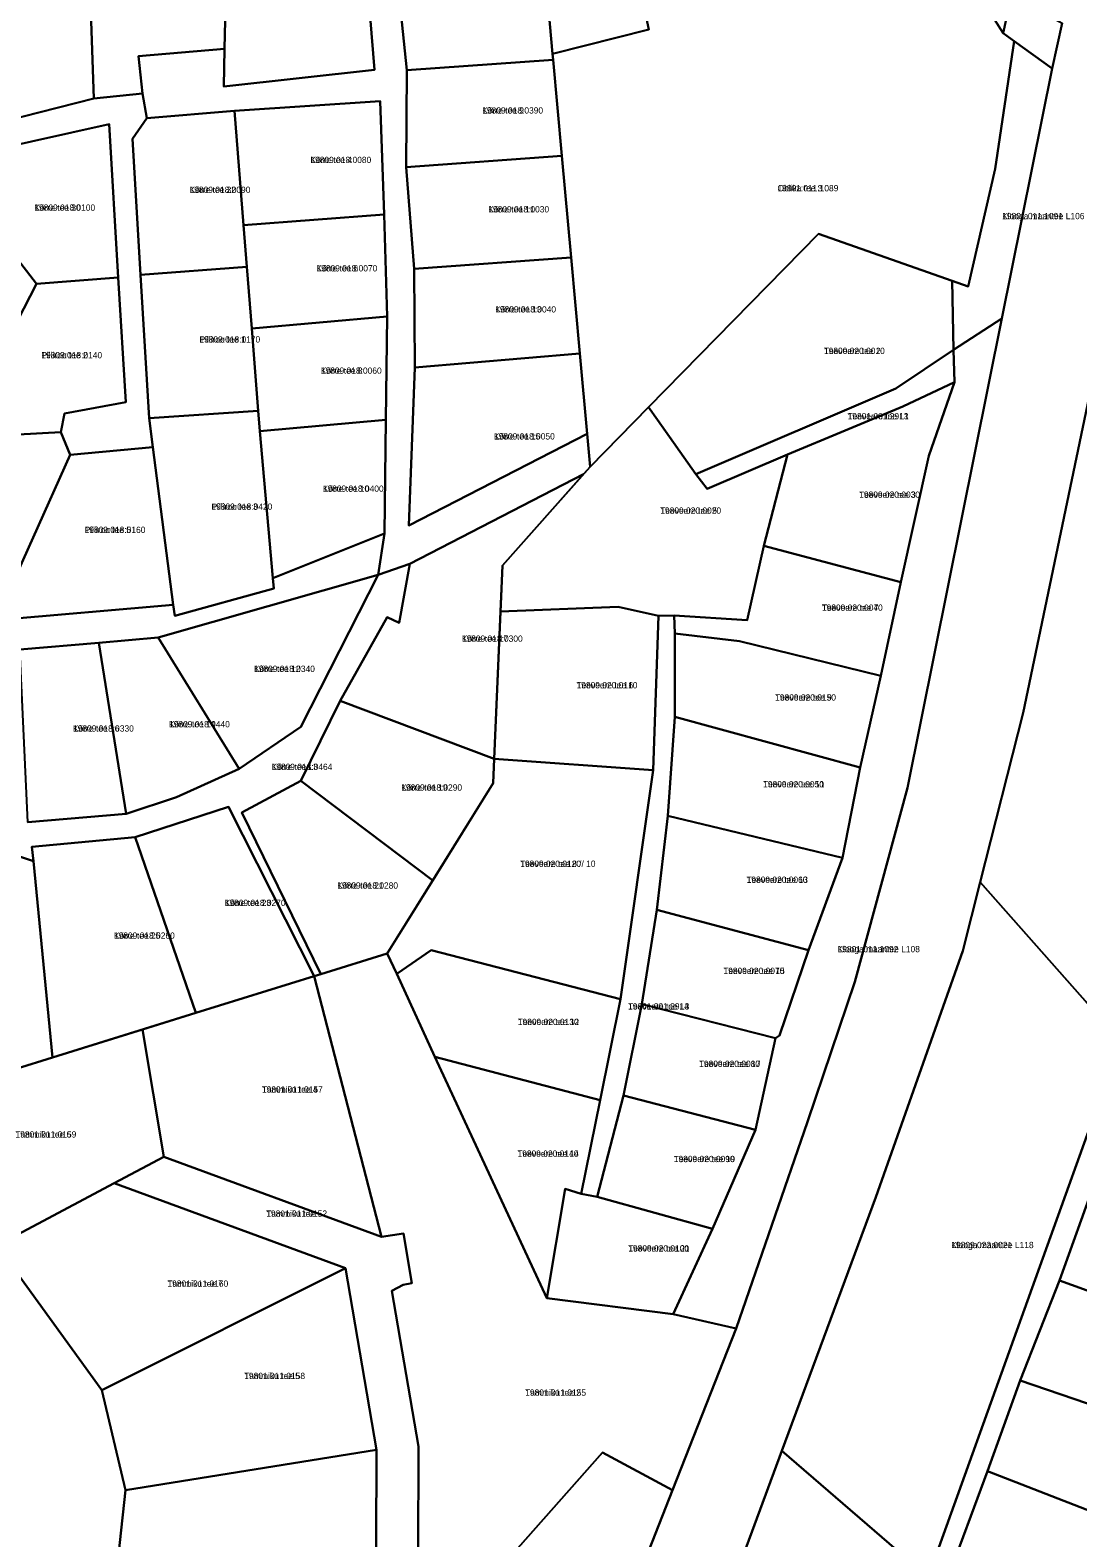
# Model space of a CAD drawing. Extents: x 516875 to 535633, y 6574491 to 6593094.
# Drawn here: x 520822.5 to 521072.3, y 6588801.2 to 6589160.7 of the extents above; entities that cross this region are included whole.
import ezdxf

# ---------------------------------------------------------------- set-up
doc = ezdxf.new("R2010")
doc.units = 0
for name, color, linetype in [('L_AADRESS', 7, 'Continuous'), ('PIIR', 7, 'Continuous'), ('TUNNUS', 7, 'Continuous')]:
    doc.layers.add(name, color=color, linetype=linetype)

msp = doc.modelspace()

# ---------------------------------------------------------------- linework, layer by layer
at = {"layer": 'PIIR'}
for points in [[(521113.51, 6589249.45), (521092.52, 6589148.09), (521087.53, 6589123.96), (521083.31, 6589112.79), (521082.46, 6589109.06), (521059.2, 6588997.94), (521048.96, 6588957.54), (521044.82, 6588941.2), (521024.12, 6588882.43), (521001.72, 6588821.95), (520983.52, 6588772.71), (520963.93, 6588719.79), (520946.47, 6588679.21), (520933.42, 6588646.06), (520903.87, 6588571.37), (520882.33, 6588519.13), (520878.26, 6588511.09), (520866.55, 6588488.59), (520853.91, 6588466.49), (520850.01, 6588439), (520821.3, 6588417.77), (520787.99, 6588379.19), (520704.64, 6588282.63)], [(520909.92, 6589174.34), (520912.31, 6589151.18), (520912.12, 6589128.02), (520914, 6589103.77), (520914.19, 6589080.27), (520912.78, 6589042.6), (520955.26, 6589064.5), (520955.98, 6589056.58), (520954.42, 6589054.82), (520913.03, 6589033.48), (520905.42, 6589030.81), (520906.95, 6589040.68), (520907.29, 6589067.78), (520907.6, 6589092.43), (520906.86, 6589116.75), (520905.91, 6589143.81), (520871.18, 6589141.44), (520850.26, 6589139.71), (520849.26, 6589145.62), (520848.29, 6589154.49), (520868.85, 6589156.27), (520868.64, 6589147.27), (520904.56, 6589151.22), (520902.12, 6589181.49)], [(521057.52, 6589173.82), (521054.48, 6589159.96), (521047.74, 6589170.69)], [(520895.13, 6588603.37), (520906.22, 6588632.62), (520914.49, 6588654.46), (520922.61, 6588675.88), (520933.69, 6588705.13), (520940.87, 6588724.07), (520975.66, 6588812.61), (520990.8, 6588851.14), (521007.83, 6588900.4), (521019.1, 6588933.81), (521031.62, 6588980.07), (521054.14, 6589091.98), (521066.15, 6589151.6), (521068.57, 6589162.41)], [(520812, 6589137.9), (520837.7, 6589144.4), (520849.26, 6589145.62), (520850.26, 6589139.71), (520846.85, 6589134.82), (520848.8, 6589102.35), (520850.85, 6589068.2), (520851.75, 6589061.26), (520831.99, 6589059.46), (520829.77, 6589064.85), (520830.67, 6589069.3), (520845.28, 6589072.02), (520843.5, 6589101.77), (520841.31, 6589138.3), (520813.82, 6589132.18)], [(520821.89, 6588971.86), (520845.4, 6588973.88), (520857.41, 6588977.79), (520872.35, 6588984.58), (520886.98, 6588994.59), (520905.42, 6589030.81), (520913.03, 6589033.48), (520910.44, 6589019.39), (520907.6, 6589020.73), (520896.4, 6589000.78), (520887.01, 6588981.75), (520872.92, 6588974.16), (520891.76, 6588935.63), (520890.23, 6588935.16), (520869.78, 6588975.54), (520847.54, 6588968.29), (520822.91, 6588966.01), (520823.25, 6588962.53), (520805.04, 6588968.64)], [(520980.19, 6588617.08), (520985.36, 6588632.85), (520998.05, 6588671.53), (521011.5, 6588712.52), (521024.12, 6588748.37), (521038.62, 6588790.13), (521036.62, 6588791.86), (521082.48, 6588919.64)], [(521076.41, 6588886.27), (521067.86, 6588862.57), (521058.55, 6588838.76), (521050.74, 6588817.12), (521040.94, 6588790.72), (521032.53, 6588767.91), (521023.22, 6588743.21), (521015.86, 6588719.54), (521007.08, 6588695.11), (521001.14, 6588675.67), (521049, 6588669.55), (521052.14, 6588689.49), (521056.24, 6588707.52), (521062.16, 6588730.29), (521071.09, 6588753.38), (521079.2, 6588776.74)]]:
    msp.add_lwpolyline(points, dxfattribs=at)
for points in [[(520868.85, 6589156.27), (520869.81, 6589196.87), (520896.77, 6589203.66), (520893.44, 6589182.16), (520902.12, 6589181.49), (520904.56, 6589151.22), (520868.64, 6589147.27)], [(520849.26, 6589145.62), (520837.7, 6589144.4), (520836.13, 6589188.38), (520869.81, 6589196.87), (520868.85, 6589156.27), (520848.29, 6589154.49)], [(520987.96, 6589174.63), (520968.11, 6589169.8), (520970.02, 6589160.88), (520947.01, 6589155.08), (520945.13, 6589176.57), (520944.66, 6589181.9), (520984.15, 6589192.47)], [(520798.28, 6589180.89), (520804.26, 6589180.35), (520836.13, 6589188.38), (520837.7, 6589144.4), (520812, 6589137.9)], [(520947.01, 6589155.08), (520970.02, 6589160.88), (520968.11, 6589169.8), (520987.96, 6589174.63), (521016.35, 6589179.45), (521032.69, 6589188.01), (521043.78, 6589179.35), (521047.74, 6589170.69), (521054.48, 6589159.96), (521057.05, 6589158.12), (521052.59, 6589127.66), (521046.1, 6589099.58), (521042.31, 6589100.91), (521010.47, 6589112.11), (520969.9, 6589070.8), (520955.98, 6589056.58), (520955.26, 6589064.5), (520953.52, 6589083.62), (520951.43, 6589106.53), (520949.23, 6589130.73), (520947.14, 6589153.64)], [(520909.92, 6589174.34), (520945.13, 6589176.57), (520947.01, 6589155.08), (520947.14, 6589153.64), (520912.31, 6589151.18)], [(521057.52, 6589173.82), (521062.76, 6589165.56), (521068.57, 6589162.41), (521066.15, 6589151.6), (521057.05, 6589158.12), (521054.48, 6589159.96)], [(521057.05, 6589158.12), (521066.15, 6589151.6), (521054.14, 6589091.98), (521042.6, 6589084.49), (521042.31, 6589100.91), (521046.1, 6589099.58), (521052.59, 6589127.66)], [(520912.31, 6589151.18), (520947.14, 6589153.64), (520949.23, 6589130.73), (520912.12, 6589128.02)], [(520871.18, 6589141.44), (520905.91, 6589143.81), (520906.86, 6589116.75), (520873.34, 6589114.23)], [(520846.85, 6589134.82), (520850.26, 6589139.71), (520871.18, 6589141.44), (520873.34, 6589114.23), (520874.13, 6589104.31), (520848.8, 6589102.35)], [(520803.45, 6589126.82), (520813.82, 6589132.18), (520841.31, 6589138.3), (520843.5, 6589101.77), (520824.03, 6589100.25)], [(520912.12, 6589128.02), (520949.23, 6589130.73), (520951.43, 6589106.53), (520914, 6589103.77)], [(520793.05, 6589117.2), (520803.45, 6589126.82), (520824.03, 6589100.25), (520816.35, 6589085.4), (520784.93, 6589100.75)], [(520874.13, 6589104.31), (520873.34, 6589114.23), (520906.86, 6589116.75), (520907.6, 6589092.43), (520875.3, 6589089.61)], [(521042.31, 6589100.91), (521042.6, 6589084.49), (521028.86, 6589075.25), (520981.21, 6589054.87), (520972.05, 6589067.78), (520969.9, 6589070.8), (521010.47, 6589112.11)], [(521083.31, 6589112.79), (521123.75, 6589097.54), (521112.7, 6589041.66), (521089.72, 6588939.81), (521082.48, 6588919.64), (521048.96, 6588957.54), (521059.2, 6588997.94), (521082.46, 6589109.06)], [(520848.8, 6589102.35), (520874.13, 6589104.31), (520875.3, 6589089.61), (520876.86, 6589069.97), (520850.85, 6589068.2)], [(520914, 6589103.77), (520951.43, 6589106.53), (520953.52, 6589083.62), (520914.19, 6589080.27)], [(520805.01, 6589063.48), (520816.35, 6589085.4), (520824.03, 6589100.25), (520843.5, 6589101.77), (520845.28, 6589072.02), (520830.67, 6589069.3), (520829.77, 6589064.85)], [(520876.86, 6589069.97), (520875.3, 6589089.61), (520907.6, 6589092.43), (520907.29, 6589067.78), (520877.23, 6589065.13)], [(521042.6, 6589084.49), (521054.14, 6589091.98), (521031.62, 6588980.07), (521019.1, 6588933.81), (521007.83, 6588900.4), (520990.8, 6588851.14), (520975.81, 6588854.53), (520985.14, 6588874.9), (520995.42, 6588898.53), (521000.2, 6588920.37), (521001.13, 6588920.98), (521008.04, 6588941.38), (521016.17, 6588963.35), (521020.41, 6588984.9), (521025.3, 6589006.75), (521030.06, 6589029.11), (521036.72, 6589059.25), (521042.89, 6589076.79)], [(520914.19, 6589080.27), (520953.52, 6589083.62), (520955.26, 6589064.5), (520912.78, 6589042.6)], [(521028.86, 6589075.25), (521042.6, 6589084.49), (521042.89, 6589076.79), (521030.52, 6589071), (521003.07, 6589059.55), (520983.87, 6589051.31), (520981.21, 6589054.87)], [(521036.72, 6589059.25), (521030.06, 6589029.11), (520997.4, 6589037.78), (521003.07, 6589059.55), (521030.52, 6589071), (521042.89, 6589076.79)], [(520972.05, 6589067.78), (520981.21, 6589054.87), (520983.87, 6589051.31), (521003.07, 6589059.55), (520997.4, 6589037.78), (520993.4, 6589020.02), (520976.05, 6589021.13), (520972.29, 6589021.1), (520962.65, 6589023.24), (520934.59, 6589022.08), (520935.06, 6589033.05), (520955.98, 6589056.58), (520969.9, 6589070.8)], [(520856.6, 6589023.71), (520851.75, 6589061.26), (520850.85, 6589068.2), (520876.86, 6589069.97), (520877.23, 6589065.13), (520880.36, 6589030.08), (520880.58, 6589027.59), (520856.94, 6589021.08)], [(520877.23, 6589065.13), (520907.29, 6589067.78), (520906.95, 6589040.68), (520880.36, 6589030.08)], [(520793.96, 6589042.11), (520805.01, 6589063.48), (520829.77, 6589064.85), (520831.99, 6589059.46), (520814.31, 6589020.02), (520783.08, 6589021.07)], [(520831.99, 6589059.46), (520851.75, 6589061.26), (520856.6, 6589023.71), (520814.31, 6589020.02)], [(520954.42, 6589054.82), (520935.06, 6589033.05), (520933.13, 6588986.99), (520896.4, 6589000.78), (520907.6, 6589020.73), (520910.44, 6589019.39), (520913.03, 6589033.48)], [(520741.58, 6589024.28), (520729.33, 6589027.15), (520697.96, 6589037.27), (520702.1, 6589045.03), (520742.8, 6589030.91), (520749, 6589028.92), (520783.08, 6589021.07), (520814.31, 6589020.02), (520856.6, 6589023.71), (520856.94, 6589021.08), (520880.58, 6589027.59), (520880.36, 6589030.08), (520906.95, 6589040.68), (520905.42, 6589030.81), (520853.02, 6589015.9), (520838.83, 6589014.66), (520820.01, 6589013.02), (520801.33, 6589014.17), (520783.59, 6589013.09), (520758.83, 6589017.81), (520755.49, 6589005.12), (520736.42, 6589012.59)], [(521030.06, 6589029.11), (521025.3, 6589006.75), (520991.6, 6589015), (520976.21, 6589016.82), (520976.05, 6589021.13), (520993.4, 6589020.02), (520997.4, 6589037.78)], [(520853.02, 6589015.9), (520905.42, 6589030.81), (520886.98, 6588994.59), (520872.35, 6588984.58)], [(520962.65, 6589023.24), (520972.29, 6589021.1), (520971.03, 6588984.3), (520933.13, 6588986.99), (520934.59, 6589022.08)], [(520972.29, 6589021.1), (520976.05, 6589021.13), (520976.21, 6589016.82), (520976.21, 6588996.97), (520974.52, 6588973.41), (520971.87, 6588950.95), (520968.33, 6588928.47), (520963.91, 6588906.72), (520957.69, 6588882.55), (520953.84, 6588883.22), (520958.36, 6588905.59), (520963.24, 6588929.67), (520971.03, 6588984.3)], [(520991.6, 6589015), (521025.3, 6589006.75), (521020.41, 6588984.9), (520976.21, 6588996.97), (520976.21, 6589016.82)], [(520820.01, 6589013.02), (520838.83, 6589014.66), (520845.4, 6588973.88), (520821.89, 6588971.86)], [(520838.83, 6589014.66), (520853.02, 6589015.9), (520872.35, 6588984.58), (520857.41, 6588977.79), (520845.4, 6588973.88)], [(520896.4, 6589000.78), (520933.13, 6588986.99), (520932.88, 6588981.16), (520918.45, 6588957.98), (520887.01, 6588981.75)], [(521020.41, 6588984.9), (521016.17, 6588963.35), (520974.52, 6588973.41), (520976.21, 6588996.97)], [(520971.03, 6588984.3), (520963.24, 6588929.67), (520918.08, 6588941.38), (520909.87, 6588935.68), (520907.61, 6588940.56), (520932.88, 6588981.16), (520933.13, 6588986.99)], [(520887.01, 6588981.75), (520918.45, 6588957.98), (520907.61, 6588940.56), (520891.76, 6588935.63), (520872.92, 6588974.16)], [(520847.54, 6588968.29), (520869.78, 6588975.54), (520890.23, 6588935.16), (520862.01, 6588926.39)], [(521016.17, 6588963.35), (521008.04, 6588941.38), (520971.87, 6588950.95), (520974.52, 6588973.41)], [(520823.25, 6588962.53), (520827.78, 6588915.75), (520784.43, 6588902.27), (520805.04, 6588968.64)], [(520823.25, 6588962.53), (520822.91, 6588966.01), (520847.54, 6588968.29), (520862.01, 6588926.39), (520827.78, 6588915.75)], [(521048.96, 6588957.54), (521082.48, 6588919.64), (521036.62, 6588791.86), (521001.72, 6588821.95), (521024.12, 6588882.43), (521044.82, 6588941.2)], [(521008.04, 6588941.38), (521001.13, 6588920.98), (521000.2, 6588920.37), (520968.33, 6588928.47), (520971.87, 6588950.95)], [(520963.24, 6588929.67), (520958.36, 6588905.59), (520918.99, 6588915.95), (520909.87, 6588935.68), (520918.08, 6588941.38)], [(520891.76, 6588935.63), (520907.61, 6588940.56), (520909.87, 6588935.68), (520918.99, 6588915.95), (520945.64, 6588858.37), (520975.81, 6588854.53), (520990.8, 6588851.14), (520975.66, 6588812.61), (520958.91, 6588821.58), (520914.95, 6588771.86), (520915.08, 6588823.04), (520908.72, 6588860.16), (520911.4, 6588861.58), (520913.49, 6588861.94), (520911.47, 6588873.77), (520906.24, 6588873.02), (520890.23, 6588935.16)], [(520862.01, 6588926.39), (520890.23, 6588935.16), (520906.24, 6588873.02), (520854.33, 6588892.08), (520849.24, 6588922.42)], [(521000.2, 6588920.37), (520995.42, 6588898.53), (520963.91, 6588906.72), (520968.33, 6588928.47)], [(520784.43, 6588902.27), (520827.78, 6588915.75), (520849.24, 6588922.42), (520854.33, 6588892.08), (520842.48, 6588885.78), (520814.52, 6588870.91), (520779.62, 6588900.77)], [(520958.36, 6588905.59), (520953.84, 6588883.22), (520950, 6588884.46), (520945.64, 6588858.37), (520918.99, 6588915.95)], [(520995.42, 6588898.53), (520985.14, 6588874.9), (520957.69, 6588882.55), (520963.91, 6588906.72)], [(520769.51, 6588897.67), (520779.62, 6588900.77), (520814.52, 6588870.91), (520839.55, 6588836.4), (520845.25, 6588812.63), (520842.85, 6588790.6), (520838.33, 6588749.48), (520874.94, 6588741.54), (520872.74, 6588738.96), (520831.43, 6588747.99), (520808.6, 6588752.98), (520786.44, 6588757.82), (520762.68, 6588763.01), (520739.61, 6588768.06), (520713.78, 6588773.7), (520678.93, 6588781.32), (520677.03, 6588781.59), (520677.94, 6588783.37), (520690.55, 6588811.8), (520703.68, 6588841.57), (520721.67, 6588882.21), (520722.36, 6588884)], [(520854.33, 6588892.08), (520906.24, 6588873.02), (520911.47, 6588873.77), (520913.49, 6588861.94), (520911.4, 6588861.58), (520908.72, 6588860.16), (520915.08, 6588823.04), (520914.95, 6588771.86), (520887.7, 6588741.05), (520885.67, 6588736.13), (520876.15, 6588738.22), (520872.74, 6588738.96), (520874.94, 6588741.54), (520904.92, 6588776.53), (520905.04, 6588822.21), (520897.63, 6588865.53), (520842.48, 6588885.78)], [(520842.48, 6588885.78), (520897.63, 6588865.53), (520839.55, 6588836.4), (520814.52, 6588870.91)], [(520953.84, 6588883.22), (520957.69, 6588882.55), (520985.14, 6588874.9), (520975.81, 6588854.53), (520945.64, 6588858.37), (520950, 6588884.46)], [(521114.66, 6588872.58), (521105.75, 6588848.88), (521067.86, 6588862.57), (521076.41, 6588886.27)], [(520897.63, 6588865.53), (520905.04, 6588822.21), (520845.25, 6588812.63), (520839.55, 6588836.4)], [(521105.75, 6588848.88), (521096.91, 6588825.62), (521058.55, 6588838.76), (521067.86, 6588862.57)], [(521096.91, 6588825.62), (521088.13, 6588802.57), (521050.74, 6588817.12), (521058.55, 6588838.76)], [(520905.04, 6588822.21), (520904.92, 6588776.53), (520842.85, 6588790.6), (520845.25, 6588812.63)], [(520975.66, 6588812.61), (520940.87, 6588724.07), (520885.67, 6588736.13), (520887.7, 6588741.05), (520914.95, 6588771.86), (520958.91, 6588821.58)], [(521001.72, 6588821.95), (521036.62, 6588791.86), (521038.62, 6588790.13), (521024.12, 6588748.37), (521021.65, 6588749.85), (520983.52, 6588772.71)], [(521088.13, 6588802.57), (521079.2, 6588776.74), (521040.94, 6588790.72), (521050.74, 6588817.12)]]:
    msp.add_lwpolyline(points, close=True, dxfattribs=at)

# ---------------------------------------------------------------- texts
at = {"layer": 'L_AADRESS'}
for s, p in [('Kõrre tee 9', (520930.27, 6589140.83)), ('Kõrre tee 4', (520889.3, 6589129.02)), ('Kõrre tee 32', (520860.49, 6589121.91)), ('Oblika tee 3', (521000.67, 6589122.29)), ('Kõrre tee 30', (520823.48, 6589117.65)), ('Kõrre tee 11', (520931.71, 6589117.25)), ('Klooga maantee L106', (521054.23, 6589115.64)), ('Kõrre tee 6', (520890.75, 6589103.18)), ('Kõrre tee 13', (520933.36, 6589093.4)), ('Pilliroo tee 1', (520862.83, 6589086.23)), ('Pilliroo tee 2', (520825.14, 6589082.47)), ('Teeveere tee 2', (521011.74, 6589083.49)), ('Kõrre tee 8', (520891.79, 6589078.78)), ('Teeveere tee L1', (521017.38, 6589067.9)), ('Kõrre tee 15', (520933.06, 6589063.11)), ('Kõrre tee 10', (520892.26, 6589050.64)), ('Teeveere tee 3', (521020.14, 6589049.21)), ('Pilliroo tee 3', (520865.71, 6589046.35)), ('Teeveere tee 5', (520972.72, 6589045.41)), ('Pilliroo tee 5', (520835.46, 6589040.82)), ('Teeveere tee 7', (521011.25, 6589022.27)), ('Kõrre tee 17', (520925.41, 6589014.88)), ('Kõrre tee 12', (520875.87, 6589007.69)), ('Teeveere tee 6', (520952.76, 6589003.77)), ('Teeveere tee 9', (521000.1, 6589000.86)), ('Kõrre tee 14', (520855.59, 6588994.47)), ('Kõrre tee 16', (520832.7, 6588993.46)), ('Kõrre tee L3', (520880.03, 6588984.32)), ('Kõrre tee 19', (520910.96, 6588979.38)), ('Teeveere tee 11', (520997.24, 6588980.16)), ('Teeveere tee 8 // 10', (520939.32, 6588961.21)), ('Kõrre tee 21', (520895.69, 6588956.02)), ('Teeveere tee 13', (520993.3, 6588957.4)), ('Kõrre tee 23', (520868.88, 6588951.89)), ('Kõrre tee 25', (520842.46, 6588944.07)), ('Klooga maantee L108', (521014.98, 6588940.85)), ('Teeveere tee 15', (520987.78, 6588935.66)), ('Teeveere tee L3', (520965.03, 6588927.2)), ('Teeveere tee 12', (520938.75, 6588923.49)), ('Teeveere tee 17', (520981.99, 6588913.5)), ('Tammiku tee 4', (520877.74, 6588907.38)), ('Tammiku tee 6', (520818.99, 6588896.67)), ('Teeveere tee 14', (520938.68, 6588892.09)), ('Teeveere tee 19', (520975.94, 6588890.81)), ('Tammiku tee', (520878.78, 6588877.78)), ('Teeveere tee 21', (520965.08, 6588869.5)), ('Klooga maantee L118', (521042.1, 6588870.3)), ('Tammiku tee 7', (520855.21, 6588861.09)), ('Tammiku tee 5', (520873.52, 6588839.08)), ('Tammiku tee 2', (520940.51, 6588835.11))]:
    msp.add_text(s, height=1.5, dxfattribs=at).set_placement(p)
at = {"layer": 'TUNNUS'}
for s, p in [('19809:018:0390', (520930.27, 6589140.83)), ('19809:018:0080', (520889.3, 6589129.02)), ('19809:018:0090', (520860.49, 6589121.91)), ('19801:011:1089', (521000.67, 6589122.29)), ('19809:018:0100', (520823.48, 6589117.65)), ('19809:018:0030', (520931.71, 6589117.25)), ('19801:011:1091', (521054.23, 6589115.64)), ('19809:018:0070', (520890.75, 6589103.18)), ('19809:018:0040', (520933.36, 6589093.4)), ('19809:018:0170', (520862.83, 6589086.23)), ('19809:018:0140', (520825.14, 6589082.47)), ('19809:020:0010', (521011.74, 6589083.49)), ('19809:018:0060', (520891.79, 6589078.78)), ('19801:001:2913', (521017.38, 6589067.9)), ('19809:018:0050', (520933.06, 6589063.11)), ('19809:018:0400', (520892.26, 6589050.64)), ('19809:020:0030', (521020.14, 6589049.21)), ('19809:018:0420', (520865.71, 6589046.35)), ('19809:020:0020', (520972.72, 6589045.41)), ('19809:018:0160', (520835.46, 6589040.82)), ('19809:020:0040', (521011.25, 6589022.27)), ('19809:018:0300', (520925.41, 6589014.88)), ('19809:018:0340', (520875.87, 6589007.69)), ('19809:020:0110', (520952.76, 6589003.77)), ('19809:020:0150', (521000.1, 6589000.86)), ('19809:018:0440', (520855.59, 6588994.47)), ('19809:018:0330', (520832.7, 6588993.46)), ('19809:018:0464', (520880.03, 6588984.32)), ('19809:018:0290', (520910.96, 6588979.38)), ('19809:020:0050', (520997.24, 6588980.16)), ('19809:020:0120', (520939.32, 6588961.21)), ('19809:018:0280', (520895.69, 6588956.02)), ('19809:020:0060', (520993.3, 6588957.4)), ('19809:018:0270', (520868.88, 6588951.89)), ('19809:018:0260', (520842.46, 6588944.07)), ('19801:011:1092', (521014.98, 6588940.85)), ('19809:020:0070', (520987.78, 6588935.66)), ('19801:001:2914', (520965.03, 6588927.2)), ('19809:020:0130', (520938.75, 6588923.49)), ('19809:020:0080', (520981.99, 6588913.5)), ('19801:011:0157', (520877.74, 6588907.38)), ('19801:011:0159', (520818.99, 6588896.67)), ('19809:020:0140', (520938.68, 6588892.09)), ('19809:020:0090', (520975.94, 6588890.81)), ('19801:011:0152', (520878.78, 6588877.78)), ('19809:020:0100', (520965.08, 6588869.5)), ('19809:022:0021', (521042.1, 6588870.3)), ('19801:011:0160', (520855.21, 6588861.09)), ('19801:011:0158', (520873.52, 6588839.08)), ('19801:011:0155', (520940.51, 6588835.11))]:
    msp.add_text(s, height=1.5, dxfattribs=at).set_placement(p)

doc.saveas('drawing.dxf')
